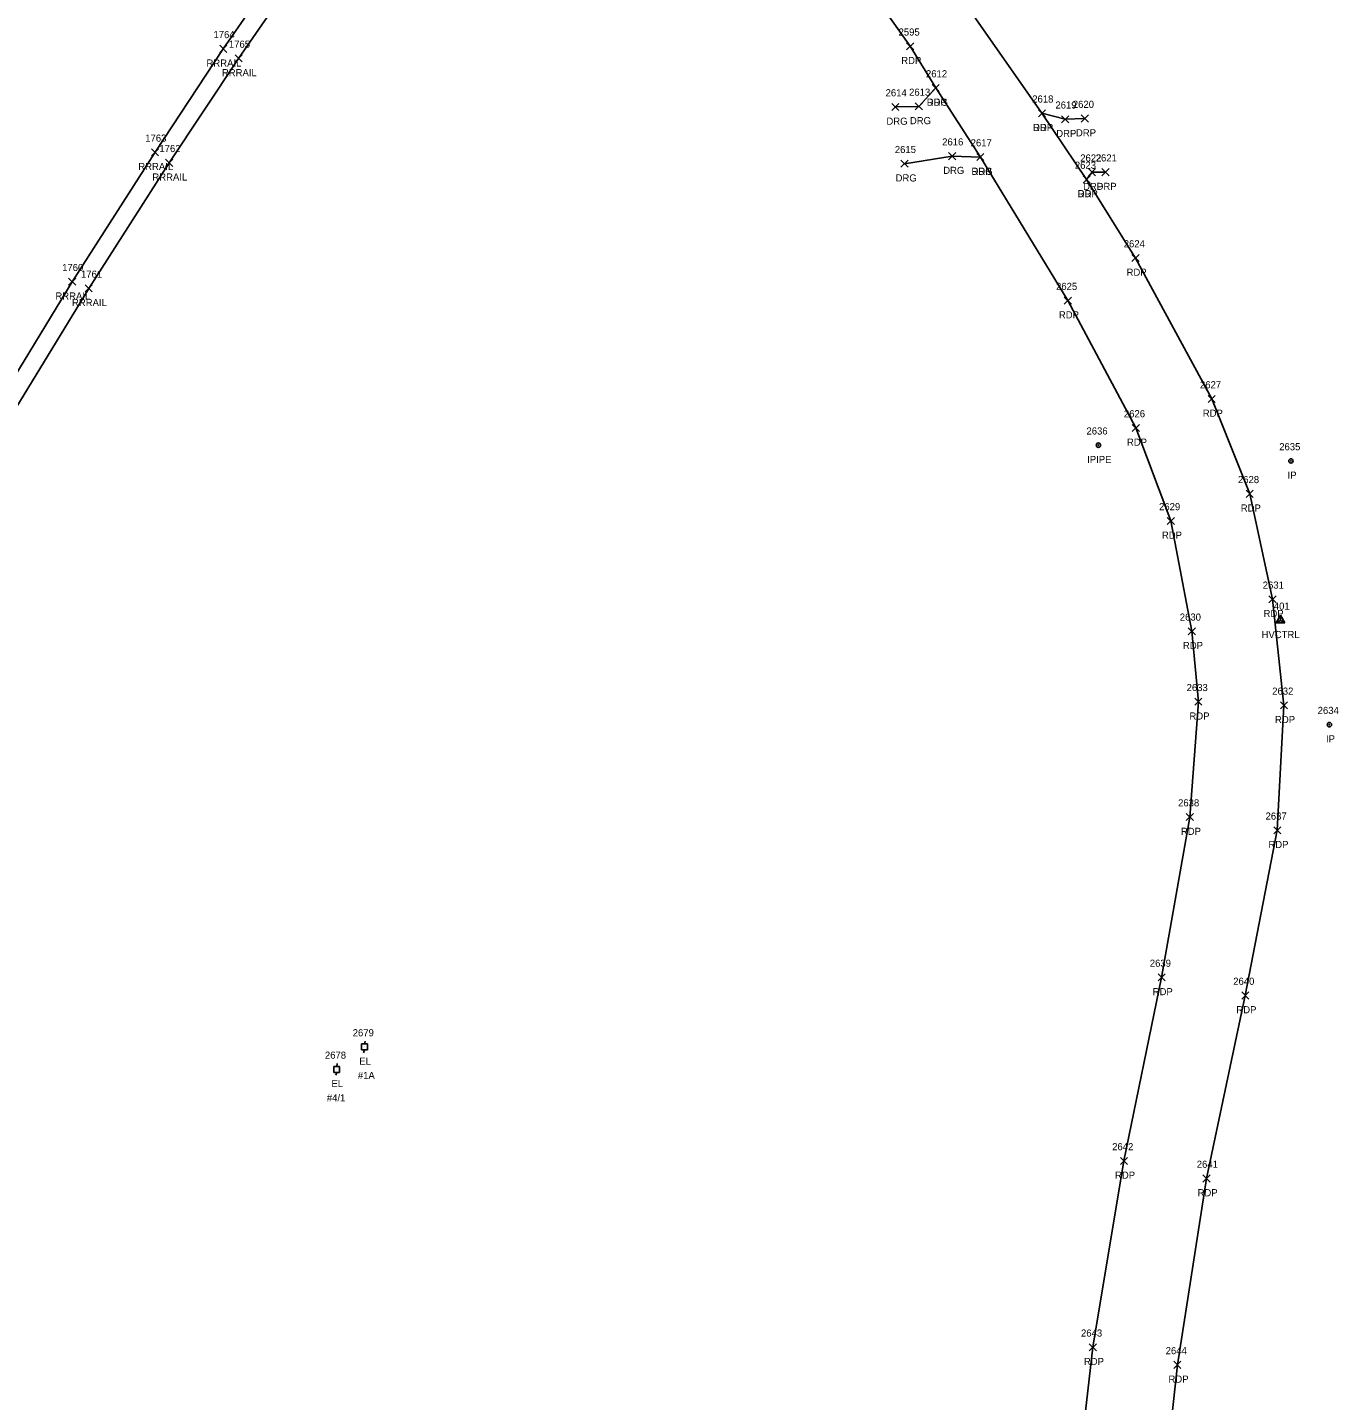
# Model space of a CAD drawing. Extents: x 1767353 to 1772625, y 740790 to 747702.
# Drawn here: x 1772120.9 to 1772489.4, y 746930.1 to 747316.1 of the extents above; entities that cross this region are included whole.
import ezdxf

# ---------------------------------------------------------------- set-up
doc = ezdxf.new("R2010")
doc.units = 0
for name, color, linetype in [('C_A', 7, 'Continuous'), ('C_I', 7, 'Continuous'), ('CPSM', 7, 'Continuous'), ('M_A', 7, 'Continuous'), ('M_I', 7, 'Continuous'), ('MPIP', 7, 'Continuous'), ('MPIR', 7, 'Continuous'), ('P_A', 7, 'Continuous'), ('P_I', 7, 'Continuous'), ('P_TIC', 7, 'Continuous'), ('PET', 7, 'Continuous'), ('R_A', 7, 'Continuous'), ('R_I', 7, 'Continuous'), ('R_TIC', 7, 'Continuous'), ('RDG', 7, 'Continuous'), ('RDP', 7, 'Continuous'), ('RR', 7, 'Continuous'), ('U_A', 7, 'Continuous'), ('U_C', 7, 'Continuous'), ('U_I', 7, 'Continuous'), ('UEPT', 7, 'Continuous')]:
    doc.layers.add(name, color=color, linetype=linetype)

msp = doc.modelspace()

# ---------------------------------------------------------------- linework, layer by layer
at = {"layer": 'CPSM'}
for p, q in [((1772471.87, 747148.74), (1772473.12, 747150.91)), ((1772471.87, 747148.74), (1772473.12, 747150.91)), ((1772471.87, 747148.74), (1772473.12, 747150.91)), ((1772471.87, 747148.74), (1772473.12, 747149.46)), ((1772471.87, 747148.74), (1772473.12, 747149.46)), ((1772471.87, 747148.74), (1772473.12, 747149.46)), ((1772474.37, 747148.74), (1772473.12, 747150.91)), ((1772473.12, 747149.46), (1772473.12, 747150.91)), ((1772474.37, 747148.74), (1772473.12, 747150.91)), ((1772473.12, 747149.46), (1772473.12, 747150.91)), ((1772474.37, 747148.74), (1772473.12, 747150.91)), ((1772473.12, 747149.46), (1772473.12, 747150.91)), ((1772473.12, 747149.46), (1772473.12, 747149.46)), ((1772473.12, 747149.46), (1772474.37, 747148.74)), ((1772473.12, 747149.46), (1772473.12, 747149.46)), ((1772473.12, 747149.46), (1772474.37, 747148.74)), ((1772473.12, 747149.46), (1772473.12, 747149.46)), ((1772473.12, 747149.46), (1772474.37, 747148.74)), ((1772471.87, 747148.74), (1772474.37, 747148.74)), ((1772471.87, 747148.74), (1772474.37, 747148.74)), ((1772471.87, 747148.74), (1772474.37, 747148.74))]:
    msp.add_line(p, q, dxfattribs=at)
at = {"layer": 'MPIP'}
for radius in [0.625, 0.0833]:
    msp.add_circle((1772421.94, 747198.7), radius, dxfattribs=at)
at = {"layer": 'MPIR'}
for centre, radius in [((1772476.07, 747194.28), 0.625), ((1772476.07, 747194.28), 0.0833), ((1772486.88, 747120.14), 0.625), ((1772486.88, 747120.14), 0.0833)]:
    msp.add_circle(centre, radius, dxfattribs=at)
at = {"layer": 'P_TIC'}
for points in [[(1772368.01, 747309.86), (1772370.01, 747311.86)], [(1772370.01, 747309.86), (1772368.01, 747311.86)], [(1772375.2, 747298.13), (1772377.2, 747300.13)], [(1772377.2, 747298.13), (1772375.2, 747300.13)], [(1772405.08, 747291.03), (1772407.08, 747293.03)], [(1772407.08, 747291.03), (1772405.08, 747293.03)], [(1772387.77, 747278.71), (1772389.77, 747280.71)], [(1772389.77, 747278.71), (1772387.77, 747280.71)], [(1772417.62, 747272.41), (1772419.62, 747274.41)], [(1772419.62, 747272.41), (1772417.62, 747274.41)], [(1772431.37, 747250.33), (1772433.37, 747252.33)], [(1772433.37, 747250.33), (1772431.37, 747252.33)], [(1772412.33, 747238.35), (1772414.33, 747240.35)], [(1772414.33, 747238.35), (1772412.33, 747240.35)], [(1772452.8, 747210.7), (1772454.8, 747212.7)], [(1772454.8, 747210.7), (1772452.8, 747212.7)], [(1772431.47, 747202.55), (1772433.47, 747204.55)], [(1772433.47, 747202.55), (1772431.47, 747204.55)], [(1772463.48, 747184.04), (1772465.48, 747186.04)], [(1772465.48, 747184.04), (1772463.48, 747186.04)], [(1772441.3, 747176.42), (1772443.3, 747178.42)], [(1772443.3, 747176.42), (1772441.3, 747178.42)], [(1772469.88, 747154.37), (1772471.88, 747156.37)], [(1772471.88, 747154.37), (1772469.88, 747156.37)], [(1772447.21, 747145.38), (1772449.21, 747147.38)], [(1772449.21, 747145.38), (1772447.21, 747147.38)], [(1772449.04, 747125.57), (1772451.04, 747127.57)], [(1772451.04, 747125.57), (1772449.04, 747127.57)], [(1772473.1, 747124.56), (1772475.1, 747126.56)], [(1772475.1, 747124.56), (1772473.1, 747126.56)], [(1772446.64, 747093.15), (1772448.64, 747095.15)], [(1772448.64, 747093.15), (1772446.64, 747095.15)], [(1772471.24, 747089.44), (1772473.24, 747091.44)], [(1772473.24, 747089.44), (1772471.24, 747091.44)], [(1772438.71, 747048.07), (1772440.71, 747050.07)], [(1772440.71, 747048.07), (1772438.71, 747050.07)], [(1772462.23, 747042.99), (1772464.23, 747044.99)], [(1772464.23, 747042.99), (1772462.23, 747044.99)], [(1772428.11, 746996.48), (1772430.11, 746998.48)], [(1772430.11, 746996.48), (1772428.11, 746998.48)], [(1772451.34, 746991.54), (1772453.34, 746993.54)], [(1772453.34, 746991.54), (1772451.34, 746993.54)], [(1772419.36, 746944.09), (1772421.36, 746946.09)], [(1772421.36, 746944.09), (1772419.36, 746946.09)], [(1772443.15, 746939.14), (1772445.15, 746941.14)], [(1772445.15, 746939.14), (1772443.15, 746941.14)]]:
    msp.add_lwpolyline(points, dxfattribs=at)
at = {"layer": 'PET'}
for points in [[(1772248.49, 747388.68), (1772247.85, 747380.52), (1772247.94, 747371.83), (1772271.67, 747369.93), (1772298.73, 747364.09), (1772330.57, 747351.94), (1772345.39, 747340.22), (1772358.44, 747325.87), (1772369.01, 747310.86), (1772376.2, 747299.13), (1772388.77, 747279.71), (1772413.33, 747239.35), (1772432.47, 747203.55), (1772442.3, 747177.42), (1772448.21, 747146.38), (1772450.04, 747126.57), (1772447.64, 747094.15), (1772439.71, 747049.07), (1772429.11, 746997.48), (1772420.36, 746945.09), (1772413.46, 746884.56)], [(1772423.02, 747369.36), (1772400.57, 747364.65), (1772389.16, 747356.08), (1772385.19, 747348.04), (1772381.79, 747336.4), (1772385.54, 747321.41), (1772406.08, 747292.03), (1772418.62, 747273.41), (1772432.37, 747251.33), (1772453.8, 747211.7), (1772464.48, 747185.04), (1772470.88, 747155.37), (1772474.1, 747125.56), (1772472.24, 747090.44), (1772463.23, 747043.99), (1772452.34, 746992.54), (1772444.15, 746940.14), (1772438.17, 746885.19)]]:
    msp.add_lwpolyline(points, dxfattribs=at)
at = {"layer": 'R_TIC'}
for points in [[(1772174.9, 747309.14), (1772176.9, 747311.14)], [(1772176.9, 747309.14), (1772174.9, 747311.14)], [(1772179.23, 747306.44), (1772181.23, 747308.44)], [(1772181.23, 747306.44), (1772179.23, 747308.44)], [(1772375.2, 747298.13), (1772377.2, 747300.13)], [(1772377.2, 747298.13), (1772375.2, 747300.13)], [(1772363.85, 747292.79), (1772365.85, 747294.79)], [(1772365.85, 747292.79), (1772363.85, 747294.79)], [(1772370.45, 747292.95), (1772372.45, 747294.95)], [(1772372.45, 747292.95), (1772370.45, 747294.95)], [(1772405.08, 747291.03), (1772407.08, 747293.03)], [(1772407.08, 747291.03), (1772405.08, 747293.03)], [(1772411.6, 747289.34), (1772413.6, 747291.34)], [(1772413.6, 747289.34), (1772411.6, 747291.34)], [(1772417.14, 747289.54), (1772419.14, 747291.54)], [(1772419.14, 747289.54), (1772417.14, 747291.54)], [(1772155.72, 747280.04), (1772157.72, 747282.04)], [(1772157.72, 747280.04), (1772155.72, 747282.04)], [(1772379.82, 747278.97), (1772381.82, 747280.97)], [(1772381.82, 747278.97), (1772379.82, 747280.97)], [(1772387.77, 747278.71), (1772389.77, 747280.71)], [(1772389.77, 747278.71), (1772387.77, 747280.71)], [(1772159.69, 747277.1), (1772161.69, 747279.1)], [(1772161.69, 747277.1), (1772159.69, 747279.1)], [(1772366.44, 747276.84), (1772368.44, 747278.84)], [(1772368.44, 747276.84), (1772366.44, 747278.84)], [(1772417.62, 747272.41), (1772419.62, 747274.41)], [(1772419.62, 747272.41), (1772417.62, 747274.41)], [(1772419.14, 747274.45), (1772421.14, 747276.45)], [(1772421.14, 747274.45), (1772419.14, 747276.45)], [(1772422.92, 747274.47), (1772424.92, 747276.47)], [(1772424.92, 747274.47), (1772422.92, 747276.47)], [(1772132.43, 747243.66), (1772134.43, 747245.66)], [(1772134.43, 747243.66), (1772132.43, 747245.66)], [(1772137.09, 747241.79), (1772139.09, 747243.79)], [(1772139.09, 747241.79), (1772137.09, 747243.79)]]:
    msp.add_lwpolyline(points, dxfattribs=at)
at = {"layer": 'RDG'}
for points in [[(1772376.2, 747299.13), (1772371.45, 747293.95), (1772364.85, 747293.79)], [(1772367.44, 747277.84), (1772380.82, 747279.97), (1772388.77, 747279.71)]]:
    msp.add_lwpolyline(points, dxfattribs=at)
at = {"layer": 'RDP'}
for points in [[(1772406.08, 747292.03), (1772412.6, 747290.34), (1772418.14, 747290.54)], [(1772423.92, 747275.47), (1772420.14, 747275.45), (1772418.62, 747273.41)]]:
    msp.add_lwpolyline(points, dxfattribs=at)
at = {"layer": 'RR'}
for points in [[(1771960.76, 746895.46), (1771976.57, 746936.04), (1771991.76, 746972.7), (1772003.71, 747000.43), (1772025.97, 747048.7), (1772044.45, 747086.9), (1772066.42, 747128.97), (1772087.05, 747166.47), (1772110.84, 747207.58), (1772133.43, 747244.66), (1772156.72, 747281.04), (1772175.9, 747310.14), (1772194.46, 747336.8), (1772219.05, 747370.3), (1772232.59, 747389.89), (1772256.2, 747421.67), (1772277.77, 747450.57), (1772416.44, 747632.57), (1772465.26, 747696.66)], [(1771963.49, 746888.34), (1771980.41, 746932.18), (1771994.59, 746967.04), (1772007.72, 746997.13), (1772029.49, 747045.02), (1772048.72, 747084.09), (1772070.77, 747126.16), (1772091.38, 747163.68), (1772115.23, 747205.31), (1772138.09, 747242.79), (1772160.69, 747278.1), (1772180.23, 747307.44), (1772199.65, 747335.62), (1772224.35, 747370.12), (1772238.38, 747389.48), (1772261.28, 747420.38), (1772281.38, 747447.15), (1772420.28, 747629.6), (1772469.26, 747693.79)]]:
    msp.add_lwpolyline(points, dxfattribs=at)
at = {"layer": 'UEPT'}
for p, q in [((1772214.78, 747028.69), (1772214.78, 747030.36)), ((1772214.78, 747030.36), (1772216.45, 747030.36)), ((1772215.78, 747031.19), (1772215.62, 747030.36)), ((1772215.62, 747029.52), (1772215.62, 747029.52)), ((1772216.45, 747030.36), (1772216.45, 747028.69)), ((1772216.45, 747028.69), (1772214.78, 747028.69)), ((1772215.37, 747027.86), (1772215.62, 747028.69)), ((1772206.96, 747022.38), (1772206.96, 747024.05)), ((1772206.96, 747024.05), (1772208.63, 747024.05)), ((1772208.63, 747022.38), (1772206.96, 747022.38)), ((1772207.55, 747021.55), (1772207.8, 747022.38)), ((1772207.96, 747024.88), (1772207.8, 747024.05)), ((1772207.8, 747023.22), (1772207.8, 747023.22)), ((1772208.63, 747024.05), (1772208.63, 747022.38))]:
    msp.add_line(p, q, dxfattribs=at)

# ---------------------------------------------------------------- texts
at = {"layer": 'C_A'}
msp.add_text('HVCTRL', height=2, dxfattribs=at).set_placement((1772467.81, 747144.46))
msp.add_text('HVCTRL', height=2, dxfattribs=at).set_placement((1772467.81, 747144.46))
msp.add_text('HVCTRL', height=2, dxfattribs=at).set_placement((1772467.81, 747144.46))
at = {"layer": 'C_I'}
msp.add_text('401', height=2, dxfattribs=at).set_placement((1772471.25, 747152.46))
msp.add_text('401', height=2, dxfattribs=at).set_placement((1772471.25, 747152.46))
msp.add_text('401', height=2, dxfattribs=at).set_placement((1772471.25, 747152.46))
at = {"layer": 'M_A'}
for s, p in [('IPIPE', (1772418.77, 747193.7)), ('IP', (1772475.12, 747189.28)), ('IP', (1772485.93, 747115.14))]:
    msp.add_text(s, height=2, dxfattribs=at).set_placement(p)
at = {"layer": 'M_I'}
for s, p in [('2636', (1772418.58, 747201.7)), ('2635', (1772472.77, 747197.28)), ('2634', (1772483.58, 747123.14))]:
    msp.add_text(s, height=2, dxfattribs=at).set_placement(p)
at = {"layer": 'P_A'}
for p in [(1772366.5, 747305.86), (1772373.68, 747294.13), (1772403.56, 747287.03), (1772386.26, 747274.71), (1772416.11, 747268.41), (1772429.86, 747246.33), (1772410.82, 747234.35), (1772451.29, 747206.7), (1772429.96, 747198.55), (1772461.96, 747180.04), (1772439.79, 747172.42), (1772468.37, 747150.37), (1772445.7, 747141.38), (1772447.53, 747121.57), (1772471.59, 747120.56), (1772445.13, 747089.15), (1772469.73, 747085.44), (1772437.19, 747044.07), (1772460.72, 747038.99), (1772426.6, 746992.48), (1772449.82, 746987.54), (1772417.85, 746940.09), (1772441.64, 746935.14)]:
    msp.add_text('RDP', height=2, dxfattribs=at).set_placement(p)
at = {"layer": 'P_I'}
for s, p in [('2595', (1772365.75, 747313.86)), ('2612', (1772373.46, 747302.13)), ('2618', (1772403.34, 747295.03)), ('2617', (1772386.03, 747282.71)), ('2623', (1772415.32, 747276.41)), ('2624', (1772429.06, 747254.33)), ('2625', (1772410.03, 747242.35)), ('2627', (1772450.49, 747214.7)), ('2626', (1772429.11, 747206.55)), ('2628', (1772461.17, 747188.04)), ('2629', (1772438.99, 747180.42)), ('2631', (1772468.14, 747158.37)), ('2630', (1772444.82, 747149.38)), ('2633', (1772446.74, 747129.57)), ('2632', (1772470.8, 747128.56)), ('2638', (1772444.33, 747097.15)), ('2637', (1772468.93, 747093.44)), ('2639', (1772436.39, 747052.07)), ('2640', (1772459.84, 747046.99)), ('2642', (1772425.81, 747000.48)), ('2641', (1772449.59, 746995.54)), ('2643', (1772417.05, 746948.09)), ('2644', (1772440.85, 746943.14))]:
    msp.add_text(s, height=2, dxfattribs=at).set_placement(p)
at = {"layer": 'R_A'}
for s, p in [('RRRAIL', (1772171.19, 747305.14)), ('RRRAIL', (1772175.52, 747302.44)), ('DRG', (1772373.68, 747294.13)), ('DRG', (1772362.34, 747288.79)), ('DRG', (1772368.94, 747288.95)), ('DRP', (1772403.56, 747287.03)), ('DRP', (1772410.09, 747285.34)), ('DRP', (1772415.63, 747285.54)), ('RRRAIL', (1772152.02, 747276.04)), ('DRG', (1772378.3, 747274.97)), ('DRG', (1772386.26, 747274.71)), ('RRRAIL', (1772155.98, 747273.1)), ('DRG', (1772364.92, 747272.84)), ('DRP', (1772416.11, 747268.41)), ('DRP', (1772417.63, 747270.45)), ('DRP', (1772421.41, 747270.47)), ('RRRAIL', (1772128.72, 747239.66)), ('RRRAIL', (1772133.38, 747237.79))]:
    msp.add_text(s, height=2, dxfattribs=at).set_placement(p)
at = {"layer": 'R_I'}
for s, p in [('1764', (1772173.15, 747313.14)), ('1765', (1772177.49, 747310.44)), ('2612', (1772373.46, 747302.13)), ('2614', (1772362.11, 747296.79)), ('2613', (1772368.71, 747296.95)), ('2618', (1772403.34, 747295.03)), ('2619', (1772409.85, 747293.34)), ('2620', (1772414.75, 747293.54)), ('1763', (1772153.98, 747284.04)), ('2616', (1772378.02, 747282.97)), ('2617', (1772386.03, 747282.71)), ('1762', (1772157.95, 747281.1)), ('2615', (1772364.7, 747280.84)), ('2622', (1772416.83, 747278.45)), ('2621', (1772421.18, 747278.47)), ('2623', (1772415.32, 747276.41)), ('1760', (1772130.61, 747247.66)), ('1761', (1772135.91, 747245.79))]:
    msp.add_text(s, height=2, dxfattribs=at).set_placement(p)
at = {"layer": 'U_A'}
for p in [(1772214.15, 747024.52), (1772206.33, 747018.22)]:
    msp.add_text('EL', height=2, dxfattribs=at).set_placement(p)
at = {"layer": 'U_C'}
for s, p in [('#1A', (1772213.74, 747020.52)), ('#4/1', (1772205.03, 747014.22))]:
    msp.add_text(s, height=2, dxfattribs=at).set_placement(p)
at = {"layer": 'U_I'}
for s, p in [('2679', (1772212.3, 747032.52)), ('2678', (1772204.49, 747026.22))]:
    msp.add_text(s, height=2, dxfattribs=at).set_placement(p)

doc.saveas('drawing.dxf')
